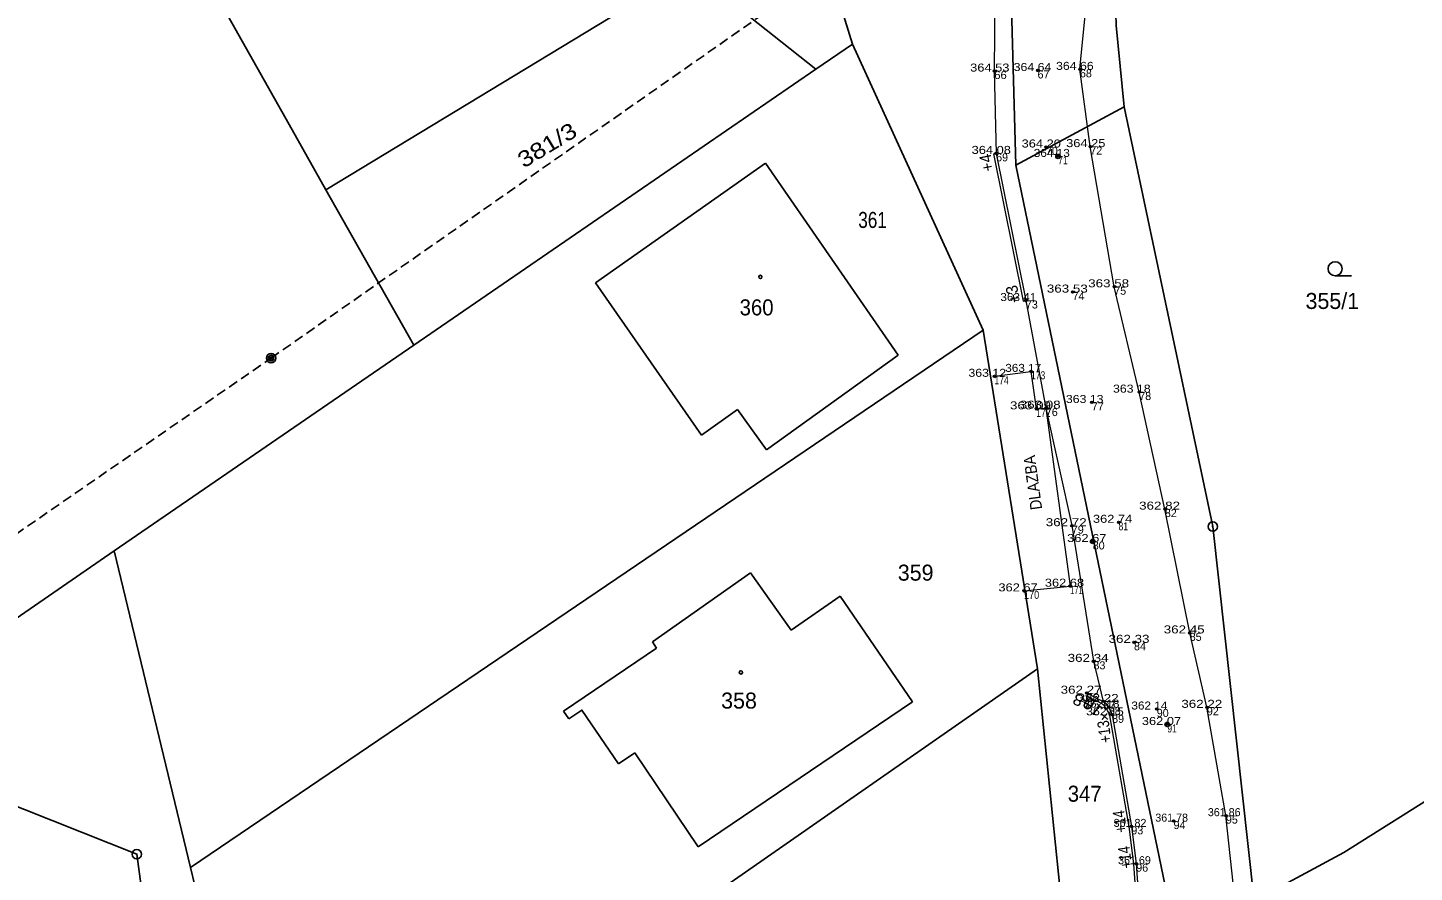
# Model space of a CAD drawing. Extents: x -592965 to -592390, y -1145071 to -1144631.
# Drawn here: x -592704.9 to -592631.3, y -1144880.5 to -1144835.7 of the extents above; entities that cross this region are included whole.
import ezdxf
from ezdxf.enums import TextEntityAlignment as Align

# ---------------------------------------------------------------- set-up
doc = ezdxf.new("R2010")
doc.units = 0
doc.header["$LTSCALE"] = 0.17
doc.header["$PDMODE"] = 32
doc.header["$PDSIZE"] = 0.085
doc.linetypes.add('MEDIUM_DASHED', pattern=[4.5, 3, -1.5])
for name, color, linetype, lineweight in [('1', 7, 'Continuous', 13), ('3', 7, 'Continuous', 13), ('4', 7, 'Continuous', 25)]:
    doc.layers.add(name, color=color, linetype=linetype, lineweight=lineweight)
doc.layers.add('2', color=7, linetype='Continuous')

msp = doc.modelspace()

# ---------------------------------------------------------------- linework, layer by layer
at = {"layer": '1'}
for p, q in [((-592653.63, -1144842.37), (-592653.49, -1144842.34)), ((-592653.63, -1144842.37), (-592652.05, -1144850.18)), ((-592652.01, -1144865.56), (-592649.56, -1144865.31)), ((-592648.74, -1144871.12), (-592647.88, -1144871.54)), ((-592648.68, -1144870.99), (-592647.8, -1144871.43)), ((-592646.05, -1144880.04), (-592646.19, -1144880.05))]:
    msp.add_line(p, q, dxfattribs=at)
for points in [[(-592641.79, -1144908.72), (-592641.16, -1144902.38), (-592640.38, -1144895.02), (-592640.15, -1144889.82), (-592640.65, -1144883.36), (-592641.29, -1144877.49), (-592642.3, -1144871.74), (-592643.21, -1144867.79), (-592644.53, -1144861.22), (-592645.89, -1144855.01), (-592647.22, -1144849.42), (-592648.49, -1144841.98), (-592649.04, -1144837.88), (-592648.65, -1144833.94), (-592647.63, -1144830.74), (-592645.94, -1144827.26), (-592642.72, -1144822.58), (-592638.67, -1144817.55), (-592634.67, -1144812.8), (-592632.14, -1144809.3), (-592630.54, -1144806.22), (-592629.58, -1144805.74)], [(-592641.51, -1144814.85), (-592646.2, -1144819.63), (-592649.98, -1144824.49), (-592652.13, -1144828.86), (-592653.48, -1144829.76), (-592654.11, -1144833.15), (-592653.56, -1144833.85), (-592653.59, -1144837.97), (-592653.49, -1144842.34), (-592651.91, -1144850.15)], [(-592652.05, -1144850.18), (-592651.91, -1144850.15), (-592650.85, -1144855.86)], [(-592653.58, -1144854.17), (-592651.64, -1144853.91), (-592651.36, -1144855.9), (-592650.85, -1144855.86), (-592649.56, -1144865.31)], [(-592650.85, -1144855.86), (-592649.47, -1144862.1), (-592648.32, -1144869.3), (-592647.8, -1144871.43)], [(-592647.47, -1144872.18), (-592646.45, -1144878.08), (-592646.19, -1144880.05), (-592646.12, -1144881.06), (-592646.02, -1144883.03), (-592645.98, -1144885.03), (-592645.96, -1144886.03), (-592645.96, -1144889.02), (-592646.04, -1144891.02), (-592646.42, -1144895.95), (-592646.76, -1144899.93), (-592647.02, -1144901.9)], [(-592647.33, -1144872.14), (-592646.31, -1144878.06), (-592646.05, -1144880.04), (-592645.98, -1144881.05), (-592645.88, -1144883.03), (-592645.84, -1144885.03), (-592645.82, -1144886.03), (-592645.82, -1144889.02), (-592645.9, -1144891.03), (-592646.28, -1144895.96), (-592646.62, -1144899.95), (-592646.88, -1144901.92)]]:
    msp.add_lwpolyline(points, dxfattribs=at)
for centre in [(-592650.2, -1144842.5), (-592648.36, -1144862.94), (-592644.4, -1144872.65)]:
    msp.add_circle(centre, 0.125, dxfattribs=at)
for centre, radius, start, end in [((-592648.5831, -1144872.4417), 1.1434, 13.23246, 52.05682), ((-592648.5233, -1144872.4194), 1.2256, 13.1771, 53.82977)]:
    msp.add_arc(centre, radius, start, end, dxfattribs=at)
at = {"layer": '2'}
for p in [(-592653.59, -1144837.97), (-592651.29, -1144837.94), (-592649.04, -1144837.88), (-592653.49, -1144842.34), (-592650.85, -1144842), (-592650.2, -1144842.5), (-592648.49, -1144841.98), (-592649.43, -1144849.7), (-592647.22, -1144849.42), (-592651.91, -1144850.15), (-592653.58, -1144854.17), (-592651.64, -1144853.91), (-592645.89, -1144855.01), (-592650.85, -1144855.86), (-592648.41, -1144855.56), (-592651.36, -1144855.9), (-592644.53, -1144861.22), (-592649.47, -1144862.1), (-592646.99, -1144861.92), (-592648.36, -1144862.94), (-592649.56, -1144865.31), (-592652.01, -1144865.56), (-592646.17, -1144868.29), (-592643.21, -1144867.79), (-592648.32, -1144869.3), (-592648.68, -1144870.99), (-592647.8, -1144871.43), (-592647.51, -1144871.73), (-592644.96, -1144871.83), (-592642.3, -1144871.74), (-592647.33, -1144872.14), (-592644.4, -1144872.65), (-592644.07, -1144877.78), (-592641.29, -1144877.49), (-592646.31, -1144878.06), (-592646.05, -1144880.04)]:
    msp.add_point(p, dxfattribs=at)
at = {"layer": '3'}
for centre, radius in [((-592653.5901, -1144837.9699), 0.0625), ((-592653.5901, -1144837.9699), 0.0395), ((-592653.5901, -1144837.9699), 0.0125), ((-592651.2901, -1144837.9399), 0.0625), ((-592651.2901, -1144837.9399), 0.0395), ((-592651.2901, -1144837.9399), 0.0125), ((-592649.0401, -1144837.8799), 0.0625), ((-592649.0401, -1144837.8799), 0.0395), ((-592649.0401, -1144837.8799), 0.0125), ((-592653.4901, -1144842.3399), 0.0625), ((-592653.4901, -1144842.3399), 0.0395), ((-592653.4901, -1144842.3399), 0.0125), ((-592650.8501, -1144841.9999), 0.0625), ((-592650.8501, -1144841.9999), 0.0395), ((-592650.8501, -1144841.9999), 0.0125), ((-592650.2001, -1144842.4999), 0.0625), ((-592650.2001, -1144842.4999), 0.0395), ((-592650.2001, -1144842.4999), 0.0125), ((-592648.4901, -1144841.9799), 0.0625), ((-592648.4901, -1144841.9799), 0.0395), ((-592648.4901, -1144841.9799), 0.0125), ((-592649.4301, -1144849.6999), 0.0625), ((-592649.4301, -1144849.6999), 0.0395), ((-592649.4301, -1144849.6999), 0.0125), ((-592647.2201, -1144849.4199), 0.0625), ((-592647.2201, -1144849.4199), 0.0395), ((-592647.2201, -1144849.4199), 0.0125), ((-592651.9101, -1144850.1499), 0.0625), ((-592651.9101, -1144850.1499), 0.0395), ((-592651.9101, -1144850.1499), 0.0125), ((-592653.5801, -1144854.1699), 0.0625), ((-592653.5801, -1144854.1699), 0.0395), ((-592653.5801, -1144854.1699), 0.0125), ((-592651.6401, -1144853.9099), 0.0625), ((-592651.6401, -1144853.9099), 0.0395), ((-592651.6401, -1144853.9099), 0.0125), ((-592645.8901, -1144855.0099), 0.0625), ((-592645.8901, -1144855.0099), 0.0395), ((-592645.8901, -1144855.0099), 0.0125), ((-592650.8501, -1144855.8599), 0.0625), ((-592650.8501, -1144855.8599), 0.0395), ((-592648.4101, -1144855.5599), 0.0625), ((-592648.4101, -1144855.5599), 0.0395), ((-592648.4101, -1144855.5599), 0.0125), ((-592651.3601, -1144855.8999), 0.0625), ((-592651.3601, -1144855.8999), 0.0395), ((-592651.3601, -1144855.8999), 0.0125), ((-592650.8501, -1144855.8599), 0.0125), ((-592644.5301, -1144861.2199), 0.0625), ((-592644.5301, -1144861.2199), 0.0395), ((-592644.5301, -1144861.2199), 0.0125), ((-592649.4701, -1144862.0999), 0.0625), ((-592649.4701, -1144862.0999), 0.0395), ((-592649.4701, -1144862.0999), 0.0125), ((-592646.9901, -1144861.9199), 0.0625), ((-592646.9901, -1144861.9199), 0.0395), ((-592646.9901, -1144861.9199), 0.0125), ((-592648.3601, -1144862.9399), 0.0625), ((-592648.3601, -1144862.9399), 0.0395), ((-592648.3601, -1144862.9399), 0.0125), ((-592649.5601, -1144865.3099), 0.0625), ((-592649.5601, -1144865.3099), 0.0395), ((-592649.5601, -1144865.3099), 0.0125), ((-592652.0101, -1144865.5599), 0.0625), ((-592652.0101, -1144865.5599), 0.0395), ((-592652.0101, -1144865.5599), 0.0125), ((-592646.1701, -1144868.2899), 0.0625), ((-592646.1701, -1144868.2899), 0.0395), ((-592646.1701, -1144868.2899), 0.0125), ((-592643.2101, -1144867.7899), 0.0625), ((-592643.2101, -1144867.7899), 0.0395), ((-592643.2101, -1144867.7899), 0.0125), ((-592648.3201, -1144869.2999), 0.0625), ((-592648.3201, -1144869.2999), 0.0395), ((-592648.3201, -1144869.2999), 0.0125), ((-592648.6801, -1144870.9899), 0.0625), ((-592648.6801, -1144870.9899), 0.0395), ((-592648.6801, -1144870.9899), 0.0125), ((-592647.8001, -1144871.4299), 0.0625), ((-592647.8001, -1144871.4299), 0.0395), ((-592647.8001, -1144871.4299), 0.0125), ((-592647.5101, -1144871.7299), 0.0625), ((-592647.5101, -1144871.7299), 0.0395), ((-592647.5101, -1144871.7299), 0.0125), ((-592644.9601, -1144871.8299), 0.0625), ((-592644.9601, -1144871.8299), 0.0395), ((-592644.9601, -1144871.8299), 0.0125), ((-592642.3001, -1144871.7399), 0.0625), ((-592642.3001, -1144871.7399), 0.0395), ((-592642.3001, -1144871.7399), 0.0125), ((-592647.3301, -1144872.1399), 0.0625), ((-592647.3301, -1144872.1399), 0.0395), ((-592647.3301, -1144872.1399), 0.0125), ((-592644.4001, -1144872.6499), 0.0625), ((-592644.4001, -1144872.6499), 0.0395), ((-592644.4001, -1144872.6499), 0.0125), ((-592644.0701, -1144877.7799), 0.0625), ((-592644.0701, -1144877.7799), 0.0395), ((-592644.0701, -1144877.7799), 0.0125), ((-592641.2901, -1144877.4899), 0.0625), ((-592641.2901, -1144877.4899), 0.0395), ((-592641.2901, -1144877.4899), 0.0125), ((-592646.3101, -1144878.0599), 0.0625), ((-592646.3101, -1144878.0599), 0.0395), ((-592646.3101, -1144878.0599), 0.0125), ((-592646.0501, -1144880.0399), 0.0625), ((-592646.0501, -1144880.0399), 0.0395), ((-592646.0501, -1144880.0399), 0.0125)]:
    msp.add_circle(centre, radius, dxfattribs=at)
at = {"layer": '4'}
for p, q in [((-592704.74, -1144816.49), (-592691.02, -1144840.81)), ((-592664.03, -1144827.05), (-592661.12, -1144836.54)), ((-592689.08, -1144844.27), (-592669.75, -1144832.57)), ((-592669.75, -1144832.57), (-592663.06, -1144837.87)), ((-592663.06, -1144837.87), (-592661.12, -1144836.54)), ((-592661.12, -1144836.54), (-592654.18, -1144851.72)), ((-592684.41, -1144852.52), (-592663.06, -1144837.87)), ((-592646.69, -1144839.87), (-592641.99, -1144862.15)), ((-592691.02, -1144840.81), (-592689.08, -1144844.27)), ((-592674.77, -1144849.21), (-592665.74, -1144842.87)), ((-592665.74, -1144842.87), (-592658.69, -1144853.06)), ((-592652.44, -1144842.96), (-592643.83, -1144884.47)), ((-592689.08, -1144844.27), (-592684.41, -1144852.52)), ((-592634.615, -1144848.84), (-592635.49, -1144848.84)), ((-592674.77, -1144849.21), (-592669.14, -1144857.29)), ((-592696.26, -1144880.25), (-592654.18, -1144851.72)), ((-592654.18, -1144851.72), (-592651.29, -1144869.7)), ((-592688.98, -1144855.65), (-592684.41, -1144852.52)), ((-592665.69, -1144858.08), (-592658.69, -1144853.06)), ((-592700.32, -1144863.43), (-592688.98, -1144855.65)), ((-592669.14, -1144857.29), (-592667.23, -1144855.93)), ((-592667.23, -1144855.93), (-592665.69, -1144858.08)), ((-592635.02, -1144879.44), (-592598.41, -1144856.35)), ((-592641.99, -1144862.15), (-592639.79, -1144882.02)), ((-592707.12, -1144868.13), (-592700.32, -1144863.43)), ((-592700.32, -1144863.43), (-592696.26, -1144880.25)), ((-592671.74, -1144868.27), (-592666.53, -1144864.61)), ((-592666.53, -1144864.61), (-592664.38, -1144867.64)), ((-592664.38, -1144867.64), (-592661.77, -1144865.85)), ((-592661.77, -1144865.85), (-592657.93, -1144871.46)), ((-592671.74, -1144868.27), (-592671.52, -1144868.6)), ((-592676.47, -1144871.94), (-592671.52, -1144868.6)), ((-592691.98, -1144897.99), (-592651.29, -1144869.7)), ((-592651.29, -1144869.7), (-592649.48, -1144887.5)), ((-592676.47, -1144871.94), (-592676.18, -1144872.36)), ((-592669.31, -1144879.14), (-592657.93, -1144871.46)), ((-592673.55, -1144874.75), (-592672.68, -1144874.16)), ((-592672.68, -1144874.16), (-592669.31, -1144879.14)), ((-592709.19, -1144875.53), (-592699.12, -1144879.54)), ((-592699.12, -1144879.54), (-592698.61, -1144883.25)), ((-592639.79, -1144882.02), (-592635.02, -1144879.44)), ((-592696.26, -1144880.25), (-592695.63, -1144882.87))]:
    msp.add_line(p, q, dxfattribs=at)
at = {"layer": '4', "linetype": 'MEDIUM_DASHED'}
msp.add_lwpolyline([(-592721.92, -1144873.86), (-592691.99, -1144853.21), (-592654.82, -1144827.23)], dxfattribs=at)
at = {"layer": '4'}
for points in [[(-592652.71, -1144833.3), (-592652.44, -1144842.96), (-592646.69, -1144839.87)], [(-592647.16, -1144834.28), (-592647.12, -1144835.56), (-592646.69, -1144839.87)], [(-592676.18, -1144872.36), (-592675.48, -1144871.89), (-592673.55, -1144874.75)]]:
    msp.add_lwpolyline(points, dxfattribs=at)
for centre, radius in [((-592635.49, -1144848.465), 0.375), ((-592666.01, -1144848.9), 0.0875), ((-592691.99, -1144853.21), 0.25), ((-592691.99, -1144853.21), 0.15), ((-592691.99, -1144853.21), 0.075), ((-592641.99, -1144862.15), 0.25), ((-592641.99, -1144862.15), 0.0164), ((-592667.04, -1144869.89), 0.0875), ((-592699.12, -1144879.54), 0.25), ((-592699.12, -1144879.54), 0.0164)]:
    msp.add_circle(centre, radius, dxfattribs=at)

# ---------------------------------------------------------------- texts
at = {"layer": '1'}
for s, p in [('+4', (-592653.6988, -1144842.7865)), ('+3', (-592652.2988, -1144849.7565))]:
    msp.add_text(s, height=0.62, rotation=101.437, dxfattribs=at).set_placement(p, align=Align.CENTER)
for s, rotation, width, p in [('DLAZBA', 97.773, 0.9, (-592651.2383, -1144859.7759)), ('+8', 153.97, 1.15, (-592648.7405, -1144871.1946)), ('+10', 140.356, 1.15, (-592647.9507, -1144871.6666)), ('+13', 97.518, 0.85, (-592647.4381, -1144872.9981)), ('+14', 97.518, 0.85, (-592646.6181, -1144877.7681)), ('+14', 97.518, 0.85, (-592646.3381, -1144879.6681))]:
    msp.add_text(s, height=0.62, rotation=rotation, dxfattribs=dict(at, width=width)).set_placement(p, align=Align.CENTER)
at = {"layer": '2'}
for s, width, p in [('66', 1.05, (-592653.59, -1144838.395)), ('71', 0.8, (-592650.2, -1144842.925)), ('174', 0.8, (-592653.58, -1144854.595)), ('173', 0.8, (-592651.64, -1144854.335)), ('172', 0.8, (-592651.36, -1144856.325)), ('81', 0.8, (-592646.99, -1144862.345)), ('171', 0.7, (-592649.56, -1144865.735)), ('170', 0.85, (-592652.01, -1144865.985)), ('91', 0.8, (-592644.4, -1144873.075))]:
    msp.add_text(s, height=0.425, dxfattribs=dict(at, width=width)).set_placement(p)
for s, p in [('67', (-592651.29, -1144838.365)), ('68', (-592649.04, -1144838.305)), ('69', (-592653.49, -1144842.765)), ('70', (-592650.85, -1144842.425)), ('72', (-592648.49, -1144842.405)), ('74', (-592649.43, -1144850.125)), ('75', (-592647.22, -1144849.845)), ('73', (-592651.91, -1144850.575)), ('78', (-592645.89, -1144855.435)), ('77', (-592648.41, -1144855.985)), ('76', (-592650.85, -1144856.285)), ('82', (-592644.53, -1144861.645)), ('79', (-592649.47, -1144862.525)), ('80', (-592648.36, -1144863.365)), ('84', (-592646.17, -1144868.715)), ('85', (-592643.21, -1144868.215)), ('83', (-592648.32, -1144869.725)), ('86', (-592648.68, -1144871.415)), ('87', (-592647.8, -1144871.855)), ('88', (-592647.51, -1144872.155)), ('90', (-592644.96, -1144872.255)), ('92', (-592642.3, -1144872.165)), ('89', (-592647.33, -1144872.565)), ('94', (-592644.07, -1144878.205)), ('95', (-592641.29, -1144877.915)), ('93', (-592646.31, -1144878.485)), ('96', (-592646.05, -1144880.465))]:
    msp.add_text(s, height=0.425, dxfattribs=at).set_placement(p)
at = {"layer": '3'}
for s, width, p in [('364 53', 1.2, (-592653.826, -1144838)), ('364 64', 1.15, (-592651.5595, -1144837.97)), ('364 66', 1.15, (-592649.3095, -1144837.91)), ('364 20', 1.2, (-592651.0945, -1144842.03)), ('364 25', 1.2, (-592648.7295, -1144842.01)), ('364 08', 1.2, (-592653.748, -1144842.37)), ('364 13', 1.1, (-592650.5345, -1144842.53)), ('363 58', 1.25, (-592647.516, -1144849.45)), ('363 41', 1.1, (-592652.31, -1144850.18)), ('363 53', 1.25, (-592649.7095, -1144849.73)), ('363 17', 1.1, (-592652.05, -1144853.94)), ('363 12', 1.15, (-592653.9615, -1144854.2)), ('363 18', 1.15, (-592646.285, -1144855.04)), ('363 09', 1.25, (-592651.6665, -1144855.93)), ('363 08', 1.25, (-592651.1515, -1144855.89)), ('363 13', 1.15, (-592648.788, -1144855.59)), ('362 82', 1.25, (-592644.8115, -1144861.25)), ('362 72', 1.25, (-592649.7685, -1144862.13)), ('362 74', 1.2, (-592647.3065, -1144861.95)), ('362 67', 1.2, (-592648.6765, -1144862.97)), ('362 67', 1.2, (-592652.3265, -1144865.59)), ('362 68', 1.2, (-592649.8615, -1144865.34)), ('362 45', 1.25, (-592643.505, -1144867.82)), ('362 33', 1.25, (-592646.433, -1144868.32)), ('362 34', 1.25, (-592648.605, -1144869.33)), ('362 27', 1.25, (-592648.9785, -1144871.02)), ('362 22', 1.25, (-592648.07, -1144871.46)), ('362 18', 1.1, (-592647.8985, -1144871.76)), ('362 15', 1.15, (-592647.712, -1144872.17)), ('362 14', 1.1, (-592645.3535, -1144871.86)), ('362 22', 1.25, (-592642.57, -1144871.77)), ('362 07', 1.2, (-592644.71, -1144872.68))]:
    msp.add_text(s, height=0.425, dxfattribs=dict(at, width=width)).set_placement(p, align=Align.CENTER)
for s, p in [('361 86', (-592641.379, -1144877.52)), ('361 82', (-592646.3805, -1144878.09)), ('361 78', (-592644.1705, -1144877.81)), ('361 69', (-592646.1455, -1144880.07))]:
    msp.add_text(s, height=0.425, dxfattribs=at).set_placement(p, align=Align.CENTER)
at = {"layer": '4'}
for s, rotation, width, p in [('381/3', 31.284, 1.2, (-592678.57, -1144843.15)), ('347', 359.662, 0.95, (-592649.69, -1144876.75))]:
    msp.add_text(s, height=0.85, rotation=rotation, dxfattribs=dict(at, width=width)).set_placement(p)
for s, width, p in [('361', 0.8, (-592660.81, -1144846.3)), ('360', 0.95, (-592667.11, -1144850.94))]:
    msp.add_text(s, height=0.85, dxfattribs=dict(at, width=width)).set_placement(p)
for s, p in [('355/1', (-592637.06, -1144850.6)), ('359', (-592658.71, -1144865.02)), ('358', (-592668.09, -1144871.81))]:
    msp.add_text(s, height=0.85, dxfattribs=at).set_placement(p)

doc.saveas('drawing.dxf')
